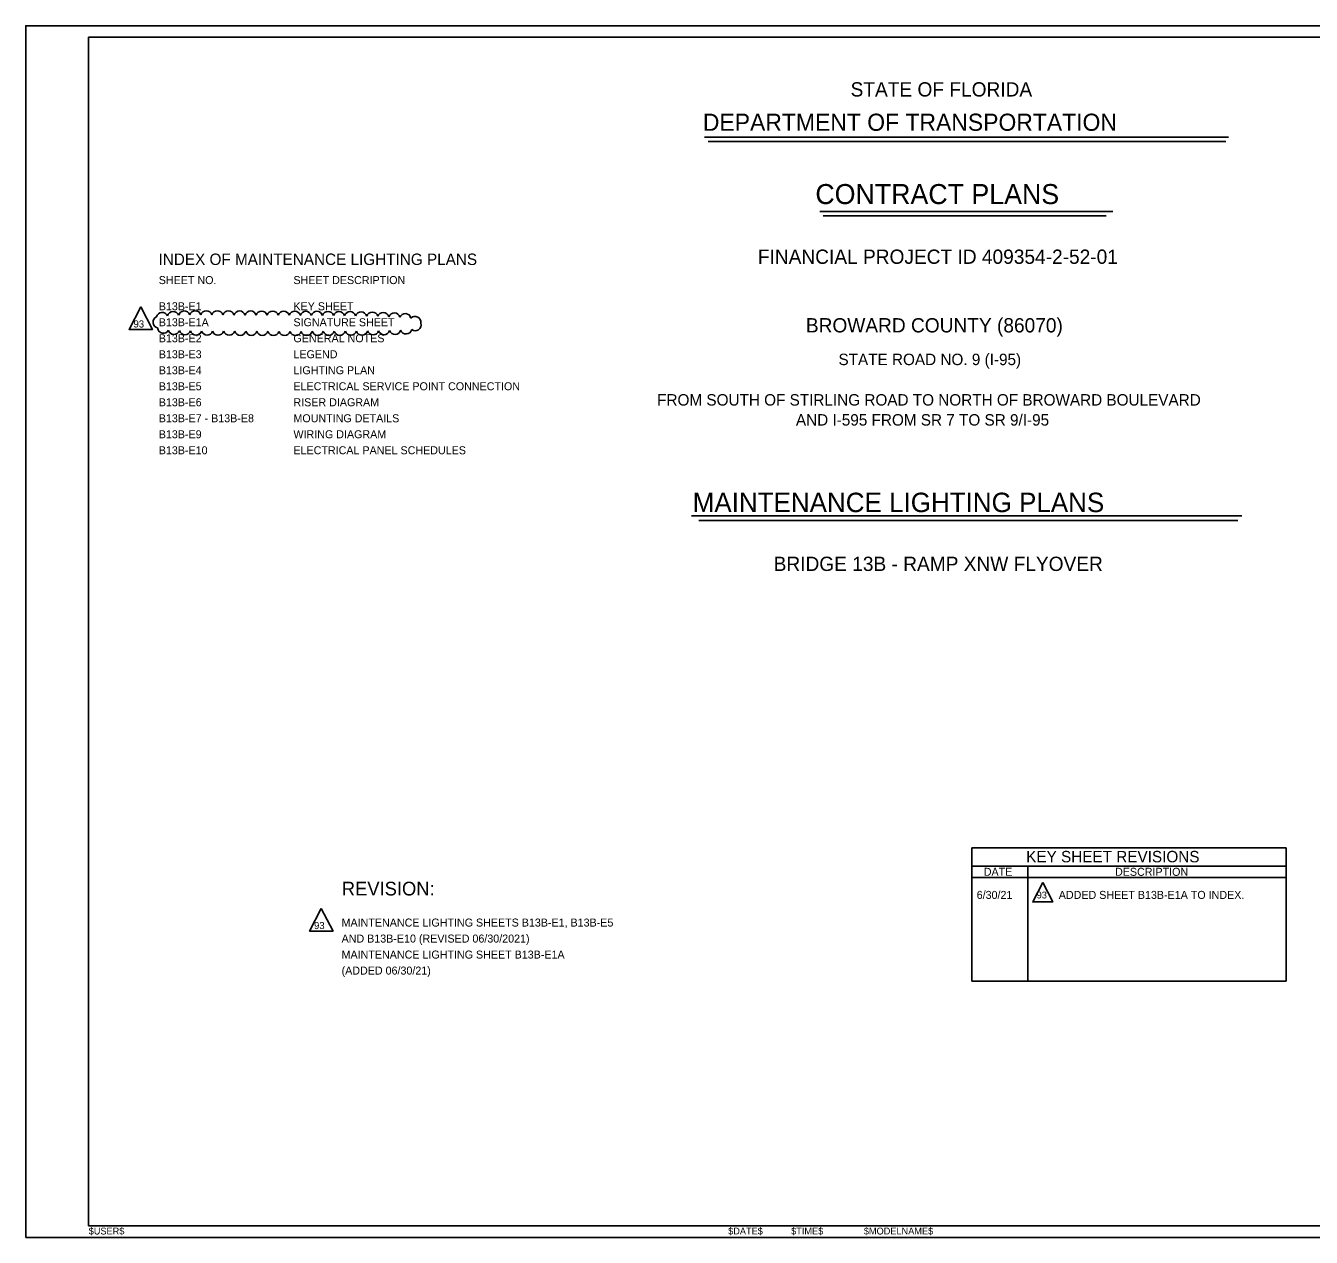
# Model space of a CAD drawing. Extents: x -820.2 to -798.1, y -2199.1 to -2188.5.
# Drawn here: x -820.23 to -808.98, y -2199.12 to -2188.52 of the extents above; entities that cross this region are included whole.
import ezdxf

# ---------------------------------------------------------------- set-up
doc = ezdxf.new("R2010")
doc.units = 0
for name, color, linetype in [('Cloud_dp', 7, 'Continuous'), ('PlotBorder_dp', 7, 'Continuous'), ('SheetBorder_dp', 7, 'Continuous'), ('SumBoxLines_dp', 7, 'Continuous'), ('TextLabel', 7, 'Continuous'), ('TextMinor', 7, 'Continuous'), ('TextNotes', 7, 'Continuous'), ('TextTitle', 7, 'Continuous')]:
    doc.layers.add(name, color=color, linetype=linetype)

msp = doc.modelspace()

# ---------------------------------------------------------------- linework, layer by layer
at = {"layer": 'Cloud_dp'}
msp.add_lwpolyline([(-811.331, -2196.02), (-811.419, -2196.189), (-811.243, -2196.189)], close=True, dxfattribs=at)
for centre, radius, start, end in [((-819.063, -2191.118), 0.0507, 112.5945, 257.5945), ((-819.033, -2191.082), 0.0507, 22.5528, 167.5528), ((-818.937, -2191.075), 0.0507, 20.3239, 165.3239), ((-818.84, -2191.07), 0.0507, 20.3844, 165.3844), ((-818.744, -2191.068), 0.0507, 17.2339, 162.2339), ((-818.647, -2191.069), 0.0507, 17.2339, 162.2339), ((-818.551, -2191.069), 0.0507, 17.2339, 162.2339), ((-818.454, -2191.069), 0.0507, 17.2339, 162.2339), ((-818.357, -2191.07), 0.0507, 17.2339, 162.2339), ((-818.26, -2191.07), 0.0507, 17.2339, 162.2339), ((-818.164, -2191.071), 0.0507, 17.2339, 162.2339), ((-818.067, -2191.071), 0.0507, 17.2339, 162.2339), ((-817.97, -2191.072), 0.0507, 17.2339, 162.2339), ((-817.873, -2191.072), 0.0507, 17.2339, 162.2339), ((-817.777, -2191.073), 0.0507, 17.2, 162.2), ((-817.68, -2191.073), 0.0507, 17.0874, 162.0874), ((-817.583, -2191.074), 0.0507, 16.9529, 161.9529), ((-817.486, -2191.075), 0.0507, 16.7917, 161.7917), ((-817.39, -2191.076), 0.0507, 16.5939, 161.5939), ((-817.293, -2191.078), 0.0507, 16.3431, 161.3431), ((-817.196, -2191.08), 0.0507, 16.01, 161.01), ((-817.1, -2191.083), 0.0507, 15.5369, 160.5369), ((-817.003, -2191.087), 0.0507, 14.785, 159.785), ((-816.907, -2191.093), 0.0507, 13.2799, 158.2799), ((-816.822, -2191.117), 0.0508, 349.8464, 134.8464), ((-819.023, -2191.163), 0.0507, 184.7859, 329.7859), ((-818.93, -2191.175), 0.0507, 195.6457, 340.6457), ((-818.834, -2191.177), 0.0507, 196.4161, 341.4161), ((-818.737, -2191.179), 0.0507, 196.7509, 341.7509), ((-818.64, -2191.18), 0.0507, 196.9508, 341.9508), ((-818.544, -2191.181), 0.0507, 197.0876, 342.0876), ((-818.447, -2191.181), 0.0507, 197.1888, 342.1888), ((-818.35, -2191.182), 0.0507, 197.2676, 342.2676), ((-818.253, -2191.182), 0.0507, 197.3313, 342.3313), ((-818.157, -2191.182), 0.0507, 197.3841, 342.3841), ((-818.06, -2191.183), 0.0507, 197.4288, 342.4288), ((-817.963, -2191.183), 0.0507, 197.4673, 342.4673), ((-817.866, -2191.183), 0.0507, 197.5061, 342.5061), ((-817.77, -2191.183), 0.0507, 197.5739, 342.5739), ((-817.673, -2191.182), 0.0507, 197.6565, 342.6565), ((-817.576, -2191.182), 0.0507, 197.7535, 342.7535), ((-817.48, -2191.182), 0.0507, 197.87, 342.87), ((-817.383, -2191.181), 0.0507, 198.0132, 343.0132), ((-817.286, -2191.18), 0.0507, 198.1954, 343.1954), ((-817.189, -2191.178), 0.0507, 198.4382, 343.4382), ((-817.093, -2191.176), 0.0507, 198.7854, 343.7854), ((-816.996, -2191.174), 0.0507, 199.3438, 344.3438), ((-816.9, -2191.17), 0.0507, 200.4946, 345.4946), ((-816.82, -2191.142), 0.0507, 232.9415, 17.9415)]:
    msp.add_arc(centre, radius, start, end, dxfattribs=at)
at = {"layer": 'PlotBorder_dp'}
msp.add_lwpolyline([(-820.227, -2199.124), (-803.727, -2199.124), (-803.727, -2188.524), (-820.227, -2188.524)], close=True, dxfattribs=at)
at = {"layer": 'SheetBorder_dp'}
for p, q in [((-819.677, -2188.624), (-819.677, -2199.024)), ((-819.677, -2188.624), (-804.277, -2188.624)), ((-819.677, -2199.024), (-804.277, -2199.024))]:
    msp.add_line(p, q, dxfattribs=at)
at = {"layer": 'SumBoxLines_dp'}
for p, q in [((-811.951, -2195.716), (-811.951, -2196.884)), ((-811.951, -2195.716), (-809.203, -2195.716)), ((-809.203, -2195.716), (-809.203, -2196.884)), ((-811.951, -2195.876), (-809.203, -2195.876)), ((-811.461, -2195.876), (-811.461, -2196.884)), ((-811.951, -2195.976), (-809.203, -2195.976)), ((-811.951, -2196.884), (-809.203, -2196.884))]:
    msp.add_line(p, q, dxfattribs=at)
at = {"layer": 'TextNotes'}
for points in [[(-819.221, -2190.984), (-819.323, -2191.181), (-819.118, -2191.181)], [(-817.642, -2196.247), (-817.744, -2196.444), (-817.539, -2196.444)]]:
    msp.add_lwpolyline(points, close=True, dxfattribs=at)
at = {"layer": 'TextTitle'}
for p, q in [((-814.289, -2189.5), (-809.707, -2189.5)), ((-814.257, -2189.538), (-809.729, -2189.538)), ((-813.281, -2190.15), (-810.719, -2190.15)), ((-813.253, -2190.188), (-810.777, -2190.188)), ((-814.404, -2192.813), (-809.59, -2192.813)), ((-814.339, -2192.851), (-809.624, -2192.851))]:
    msp.add_line(p, q, dxfattribs=at)

# ---------------------------------------------------------------- texts
at = {"layer": 'Cloud_dp'}
msp.add_text('93', height=0.06, rotation=0, dxfattribs=at).set_placement((-811.384, -2196.159))
at = {"layer": 'TextLabel'}
for s, height, p in [('INDEX OF MAINTENANCE LIGHTING PLANS', 0.1, (-819.065, -2190.617)), ('FINANCIAL PROJECT ID 409354-2-52-01', 0.125, (-813.823, -2190.607)), ('B13B-E1', 0.07, (-819.063, -2191.013)), ('KEY SHEET', 0.07, (-817.885, -2191.013)), ('B13B-E1A', 0.07, (-819.063, -2191.153)), ('SIGNATURE SHEET', 0.07, (-817.885, -2191.153)), ('BROWARD COUNTY (86070)', 0.125, (-813.403, -2191.207)), ('B13B-E2', 0.07, (-819.063, -2191.293)), ('GENERAL NOTES', 0.07, (-817.885, -2191.293)), ('B13B-E3', 0.07, (-819.063, -2191.433)), ('LEGEND', 0.07, (-817.885, -2191.433)), ('STATE ROAD NO. 9 (I-95)', 0.1, (-813.118, -2191.493)), ('B13B-E4 ', 0.07, (-819.063, -2191.573)), ('LIGHTING PLAN', 0.07, (-817.885, -2191.573)), ('B13B-E5', 0.07, (-819.063, -2191.713)), ('ELECTRICAL SERVICE POINT CONNECTION', 0.07, (-817.885, -2191.713)), ('B13B-E6', 0.07, (-819.063, -2191.853)), ('RISER DIAGRAM', 0.07, (-817.885, -2191.853)), ('FROM SOUTH OF STIRLING ROAD TO NORTH OF BROWARD BOULEVARD', 0.1, (-814.704, -2191.847)), ('B13B-E7 - B13B-E8 ', 0.07, (-819.063, -2191.993)), ('MOUNTING DETAILS', 0.07, (-817.885, -2191.993)), ('AND I-595 FROM SR 7 TO SR 9/I-95', 0.1, (-813.49, -2192.022)), ('B13B-E9 ', 0.07, (-819.063, -2192.133)), ('WIRING DIAGRAM', 0.07, (-817.885, -2192.133)), ('B13B-E10', 0.07, (-819.063, -2192.273)), ('ELECTRICAL PANEL SCHEDULES', 0.07, (-817.885, -2192.273)), ('BRIDGE 13B - RAMP XNW FLYOVER', 0.125, (-813.685, -2193.294)), ('KEY SHEET REVISIONS', 0.1, (-811.476, -2195.843)), ('REVISION:', 0.12, (-817.462, -2196.133))]:
    msp.add_text(s, height=height, dxfattribs=at).set_placement(p)
at = {"layer": 'TextMinor'}
for s, p in [('6/30/21', (-811.909, -2196.163)), ('ADDED SHEET B13B-E1A TO INDEX.', (-811.191, -2196.163))]:
    msp.add_text(s, height=0.07, dxfattribs=at).set_placement(p)
for s, p in [('$USER$', (-819.676, -2199.099)), ('$DATE$', (-814.083, -2199.099)), ('$TIME$', (-813.532, -2199.099)), ('$MODELNAME$', (-812.896, -2199.099))]:
    msp.add_text(s, height=0.06, rotation=360, dxfattribs=at).set_placement(p)
at = {"layer": 'TextNotes'}
for s, p in [('SHEET NO.', (-819.063, -2190.784)), ('SHEET DESCRIPTION', (-817.885, -2190.784)), ('DATE', (-811.847, -2195.961)), ('DESCRIPTION', (-810.699, -2195.961)), ('MAINTENANCE LIGHTING SHEETS B13B-E1, B13B-E5 ', (-817.464, -2196.405)), ('AND B13B-E10 (REVISED 06/30/2021)', (-817.464, -2196.545)), ('MAINTENANCE LIGHTING SHEET B13B-E1A ', (-817.464, -2196.685)), ('(ADDED 06/30/21)', (-817.464, -2196.825))]:
    msp.add_text(s, height=0.07, dxfattribs=at).set_placement(p)
for p in [(-819.284, -2191.164), (-817.705, -2196.427)]:
    msp.add_text('93', height=0.0622, rotation=0, dxfattribs=at).set_placement(p)
at = {"layer": 'TextTitle'}
for s, height, p in [('STATE OF FLORIDA', 0.125, (-813.012, -2189.143)), ('DEPARTMENT OF TRANSPORTATION', 0.15, (-814.304, -2189.443)), ('CONTRACT PLANS', 0.175, (-813.32, -2190.084)), ('MAINTENANCE LIGHTING PLANS', 0.17, (-814.393, -2192.779))]:
    msp.add_text(s, height=height, dxfattribs=at).set_placement(p)

doc.saveas('drawing.dxf')
